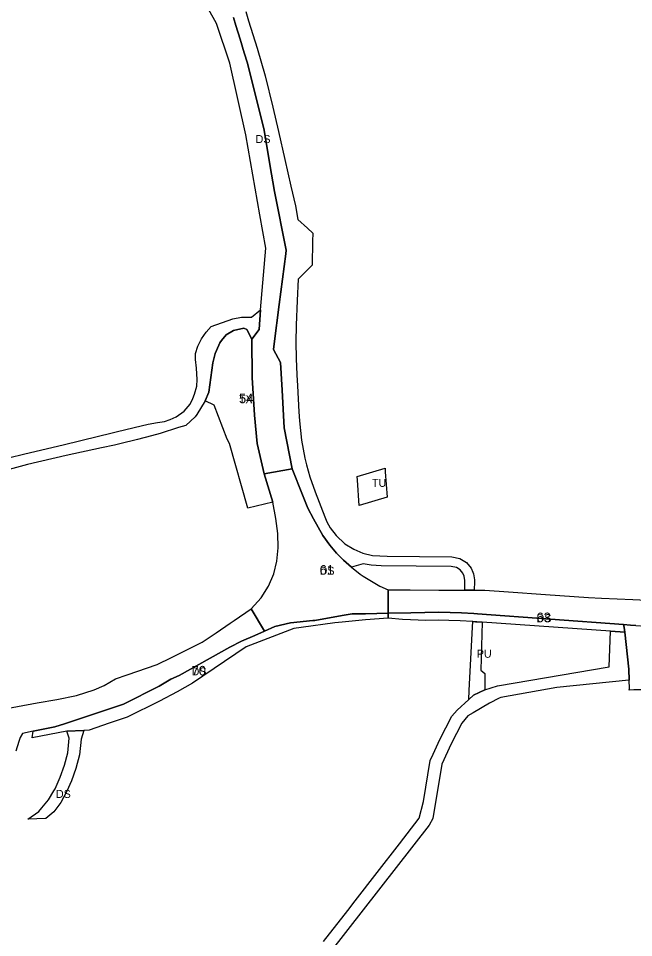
# Model space of a CAD drawing. Extents: x -535435 to -532834, y -1165802 to -1163866.
# Drawn here: x -534109 to -533724, y -1165015 to -1164441 of the extents above; entities that cross this region are included whole.
import ezdxf

# ---------------------------------------------------------------- set-up
doc = ezdxf.new("R2010")
doc.units = 0
for name, color, linetype in [('90320013', 7, 'Continuous'), ('90320023', 7, 'Continuous'), ('90380013', 7, 'Continuous'), ('90380023', 7, 'Continuous'), ('90440023', 7, 'Continuous'), ('90450013', 7, 'Continuous'), ('90450023', 7, 'Continuous'), ('ID_navrh', 7, 'Continuous')]:
    doc.layers.add(name, color=color, linetype=linetype)

msp = doc.modelspace()

# ---------------------------------------------------------------- linework, layer by layer
at = {"layer": '90320013'}
for points in [[(-533974.15, -1164440.11), (-533972.65, -1164445.05), (-533970.07, -1164453.5), (-533967.42, -1164462.17), (-533965.5, -1164468.47), (-533962.73, -1164479.54), (-533955.24, -1164509.41), (-533954.44, -1164514.16), (-533951.43, -1164531.95), (-533948.58, -1164548.78), (-533941.27, -1164585.42), (-533941.56, -1164587.64), (-533945.61, -1164619.41), (-533948.72, -1164643.84), (-533949.17, -1164647.34), (-533944.79, -1164655.52), (-533943.81, -1164672.76), (-533942.91, -1164688.74), (-533942.48, -1164696.43), (-533937.62, -1164722.08), (-533955.09, -1164725.13), (-533959.32, -1164706.09), (-533961.14, -1164688.48), (-533962.47, -1164664.91), (-533962.79, -1164640.92), (-533958.25, -1164634.91), (-533957.211, -1164622.742), (-533953.92, -1164584.19), (-533957.65, -1164563.22), (-533966.49, -1164513.4), (-533976.42, -1164468.54), (-533984.74, -1164443.86), (-533999.91, -1164416.7)], [(-533722.741, -1164819.796), (-533726.02, -1164819.56), (-533730.54, -1164819.23), (-533821.72, -1164812.62), (-533824.09, -1164812.44), (-533831.76, -1164811.89), (-533845.93, -1164811.47), (-533863.45, -1164811.86), (-533877.61, -1164812.17), (-533877.62, -1164797.66), (-533872.62, -1164797.667), (-533863.74, -1164797.68), (-533845.77, -1164797.71), (-533829.713, -1164797.731), (-533823.21, -1164797.74), (-533820.59, -1164797.75), (-533817.02, -1164797.76), (-533802.41, -1164798.81), (-533779.21, -1164800.48), (-533752.3, -1164802.43), (-533744.22, -1164802.78), (-533724.542, -1164803.644), (-533711.44, -1164804.22)]]:
    msp.add_lwpolyline(points, dxfattribs=at)
msp.add_lwpolyline([(-534067.68, -1164885.4), (-534069.42, -1164890.86), (-534070.43, -1164900.65), (-534072.79, -1164909.21), (-534075.53, -1164917.01), (-534078.29, -1164923.33), (-534082.19, -1164930.46), (-534086.44, -1164936.35), (-534091.39, -1164940.53), (-534102.62, -1164940.95), (-534095.94, -1164936.02), (-534093.96, -1164933.75), (-534089.86, -1164928.73), (-534086.47, -1164923.09), (-534085.73, -1164921.88), (-534082.42, -1164914.59), (-534079.81, -1164907.04), (-534077.66, -1164899.32), (-534076.97, -1164890.2), (-534078.33, -1164885.8)], close=True, dxfattribs=at)
at = {"layer": '90320023'}
for points in [[(-533966.526, -1164436.248), (-533964.719, -1164442.117), (-533962.096, -1164450.634), (-533959.457, -1164459.206), (-533954.432, -1164476.512), (-533949.559, -1164496.052), (-533946.1, -1164511.207), (-533942.1, -1164528.737), (-533938.311, -1164545.337), (-533935.477, -1164557.756), (-533933.924, -1164566.171), (-533928.047, -1164571.612), (-533924.633, -1164574.772), (-533924.728, -1164579.85), (-533925.006, -1164594.768), (-533928.175, -1164597.927), (-533933.845, -1164603.579), (-533934.374, -1164616.826), (-533935.021, -1164632.229), (-533935.27, -1164642.867), (-533935.108, -1164652.972), (-533934.702, -1164663.366), (-533934.278, -1164670.147), (-533933.268, -1164686.286), (-533932.906, -1164692.069), (-533931.627, -1164704.155), (-533929.632, -1164715.238), (-533928.481, -1164719.555), (-533926.509, -1164726.959), (-533923.227, -1164736.291), (-533917.13, -1164752.07), (-533915.848, -1164755.075), (-533913.837, -1164758.775), (-533910.072, -1164763.667), (-533904.657, -1164768.747), (-533899.011, -1164772.271), (-533893.292, -1164774.744), (-533887.252, -1164776.166), (-533878.083, -1164776.633), (-533837.659, -1164776.992), (-533832.654, -1164777.966), (-533828.577, -1164780.481), (-533825.628, -1164784), (-533824.518, -1164786.617), (-533824.147, -1164787.493), (-533823.649, -1164791.291), (-533823.66, -1164792.468), (-533823.713, -1164797.739), (-533829.713, -1164797.731), (-533829.653, -1164791.654), (-533829.99, -1164789.083), (-533830.802, -1164787.167), (-533832.553, -1164785.078), (-533834.874, -1164783.646), (-533838.263, -1164782.986), (-533881.993, -1164782.599), (-533888.18, -1164782.112), (-533893.097, -1164781.251), (-533900.403, -1164783.498), (-533905.409, -1164779.095), (-533909.763, -1164774.688), (-533913.989, -1164769.716), (-533918.274, -1164763.699), (-533924.264, -1164753.325), (-533927.756, -1164746.582), (-533931.134, -1164738.193), (-533937.62, -1164722.08), (-533942.48, -1164696.43), (-533942.91, -1164688.74), (-533943.81, -1164672.76), (-533944.79, -1164655.52), (-533949.17, -1164647.34), (-533948.72, -1164643.84), (-533945.61, -1164619.41), (-533941.56, -1164587.64), (-533941.27, -1164585.42), (-533948.58, -1164548.78), (-533951.43, -1164531.95), (-533954.44, -1164514.16), (-533955.24, -1164509.41), (-533962.73, -1164479.54), (-533965.5, -1164468.47), (-533967.42, -1164462.17), (-533970.07, -1164453.5), (-533972.65, -1164445.05), (-533974.15, -1164440.11)], [(-534114.899, -1164715.096), (-534104.663, -1164712.55), (-534080.73, -1164706.916), (-534058.603, -1164701.497), (-534050.857, -1164699.668), (-534047.573, -1164698.892), (-534036.347, -1164696.241), (-534027.567, -1164694.184), (-534021.634, -1164693.103), (-534017.22, -1164692.32), (-534013.67, -1164691.24), (-534010.017, -1164689.514), (-534004.94, -1164685.91), (-534001.2, -1164681.66), (-533999.598, -1164677.998), (-533998.47, -1164675.42), (-533997.1, -1164670.37), (-533996.9, -1164666.28), (-533997.34, -1164659.16), (-533997.92, -1164653.73), (-533997.86, -1164649.94), (-533996.38, -1164645.34), (-533994.23, -1164640.86), (-533991.34, -1164636.53), (-533988.116, -1164633.161), (-533974.64, -1164628.33), (-533969.29, -1164627.24), (-533963.011, -1164627.201), (-533957.211, -1164622.742), (-533958.25, -1164634.91), (-533962.79, -1164640.92), (-533965.769, -1164634.873), (-533967.69, -1164634.08), (-533974.09, -1164635.67), (-533978.83, -1164638.245), (-533981.729, -1164641.883), (-533982.7, -1164643.29), (-533984.794, -1164648.09), (-533985.58, -1164649.89), (-533987.09, -1164655.67), (-533989.59, -1164674.03), (-533991.85, -1164679.44), (-533997.187, -1164688.034), (-533998.16, -1164689.6), (-534004.077, -1164694.939), (-534008.472, -1164696.158), (-534019.931, -1164699.905), (-534025.36, -1164701.44), (-534034.205, -1164703.612), (-534045.29, -1164706.38), (-534048.46, -1164707.26), (-534056.646, -1164708.944), (-534078.701, -1164713.711), (-534102.862, -1164719.219), (-534114.467, -1164722.35)]]:
    msp.add_lwpolyline(points, dxfattribs=at)
for points in [[(-533954.918, -1164823.491), (-533963.1, -1164809.55), (-533956.938, -1164802.511), (-533952.293, -1164795.247), (-533949.047, -1164787.683), (-533947.08, -1164779.742), (-533946.273, -1164771.351), (-533946.509, -1164762.433), (-533947.667, -1164752.915), (-533949.63, -1164742.72), (-533955.09, -1164725.13), (-533937.62, -1164722.08), (-533931.134, -1164738.193), (-533927.756, -1164746.582), (-533924.264, -1164753.325), (-533918.274, -1164763.699), (-533913.989, -1164769.716), (-533909.763, -1164774.688), (-533905.409, -1164779.095), (-533900.403, -1164783.498), (-533894.971, -1164787.721), (-533893.072, -1164788.969), (-533882.672, -1164795.392), (-533877.62, -1164797.66), (-533877.61, -1164812.17), (-533891.74, -1164812.48), (-533900.11, -1164812.65), (-533906.24, -1164813.72), (-533923.29, -1164816.69), (-533924.69, -1164816.71), (-533938.49, -1164818.24), (-533948.29, -1164820.59)], [(-533877.61, -1164812.17), (-533877.617, -1164815.18), (-533891.706, -1164816.42), (-533906.182, -1164817.694), (-533910.91, -1164818.11), (-533931.848, -1164821.093), (-533936.53, -1164821.76), (-533960.78, -1164831.03), (-533966.36, -1164833.16), (-533999.79, -1164855.92), (-534009.46, -1164861.214), (-534020.45, -1164867.23), (-534040.68, -1164877.03), (-534051.898, -1164880.919), (-534064.45, -1164885.27), (-534067.68, -1164885.4), (-534078.33, -1164885.8), (-534099.92, -1164890.03), (-534099.32, -1164885.91), (-534085.85, -1164883.22), (-534079.77, -1164881.2), (-534064.74, -1164876.21), (-534042.95, -1164868.98), (-534020.66, -1164857.69), (-534013.44, -1164853.47), (-534008.11, -1164851.18), (-533976.56, -1164833.46), (-533969.12, -1164829.71), (-533960.9, -1164826.11), (-533954.918, -1164823.491), (-533948.29, -1164820.59), (-533938.49, -1164818.24), (-533924.69, -1164816.71), (-533923.29, -1164816.69), (-533906.24, -1164813.72), (-533900.11, -1164812.65), (-533891.74, -1164812.48)], [(-533877.61, -1164812.17), (-533863.45, -1164811.86), (-533845.93, -1164811.47), (-533831.76, -1164811.89), (-533824.09, -1164812.44), (-533821.72, -1164812.62), (-533730.54, -1164819.23), (-533730.04, -1164821.1), (-533729.7, -1164824.13), (-533738.69, -1164823.39), (-533818.847, -1164817.831), (-533822.155, -1164817.601), (-533822.99, -1164817.538), (-533824.567, -1164817.419), (-533824.726, -1164817.407), (-533824.861, -1164817.398), (-533832.622, -1164816.867), (-533839.714, -1164816.656), (-533846.109, -1164816.475), (-533854.091, -1164816.653), (-533863.514, -1164816.25), (-533868.666, -1164816.03), (-533877.617, -1164815.18)]]:
    msp.add_lwpolyline(points, close=True, dxfattribs=at)
at = {"layer": '90380013'}
msp.add_lwpolyline([(-533895.56, -1164744.9), (-533896.78, -1164729.16), (-533896.98, -1164726.69), (-533879.49, -1164721.65), (-533879.34, -1164723.78), (-533878.24, -1164739.68)], close=True, dxfattribs=at)
at = {"layer": '90380023'}
msp.add_lwpolyline([(-533917.983, -1165017.223), (-533902.835, -1164997.813), (-533898.225, -1164991.906), (-533884.317, -1164974.086), (-533870.466, -1164956.339), (-533858.16, -1164940.26), (-533855.511, -1164929.84), (-533851.211, -1164904.246), (-533849.336, -1164900.158), (-533846.247, -1164893.426), (-533845.178, -1164891.097), (-533837.807, -1164876.568), (-533834.51, -1164872.77), (-533827.206, -1164866.027), (-533824.163, -1164863.424), (-533817.166, -1164859.962), (-533809.264, -1164857.538), (-533739.473, -1164845.641), (-533738.69, -1164823.39), (-533729.7, -1164824.13), (-533727.12, -1164847.21), (-533726.9, -1164854), (-533727.16, -1164854.1), (-533772.11, -1164858.69), (-533807.19, -1164864.79), (-533808.265, -1164865.356), (-533814.12, -1164868.44), (-533824.38, -1164874.44), (-533827.73, -1164876.4), (-533831.54, -1164880.79), (-533838.18, -1164893.83), (-533843.98, -1164906.47), (-533849.69, -1164940.46), (-533851.83, -1164944.65), (-533913.79, -1165024.04)], dxfattribs=at)
at = {"layer": '90440023'}
msp.add_lwpolyline([(-533965.282, -1164746.513), (-533976.638, -1164706.229), (-533978.18, -1164703.55), (-533986.32, -1164682.27), (-533991.85, -1164679.44), (-533989.59, -1164674.03), (-533987.09, -1164655.67), (-533985.58, -1164649.89), (-533984.794, -1164648.09), (-533982.7, -1164643.29), (-533981.729, -1164641.883), (-533978.83, -1164638.245), (-533974.09, -1164635.67), (-533967.69, -1164634.08), (-533965.769, -1164634.873), (-533962.79, -1164640.92), (-533962.47, -1164664.91), (-533961.14, -1164688.48), (-533959.32, -1164706.09), (-533955.09, -1164725.13), (-533949.63, -1164742.72), (-533954.82, -1164744.13)], close=True, dxfattribs=at)
at = {"layer": '90450013'}
msp.add_lwpolyline([(-534121.57, -1164872.72), (-534096.94, -1164868.25), (-534084.65, -1164866.02), (-534072.3, -1164863.66), (-534061.28, -1164860.07), (-534055.1, -1164857.37), (-534047.9, -1164853.22), (-534040.68, -1164850.74), (-534021.84, -1164844.27), (-534012.98, -1164839.86), (-533996.77, -1164831.8), (-533993.8, -1164830.33), (-533985, -1164824.37), (-533976.3, -1164818.48), (-533973.78, -1164816.77), (-533963.1, -1164809.55), (-533954.918, -1164823.491), (-533960.9, -1164826.11), (-533969.12, -1164829.71), (-533976.56, -1164833.46), (-534008.11, -1164851.18), (-534013.44, -1164853.47), (-534020.66, -1164857.69), (-534042.95, -1164868.98), (-534064.74, -1164876.21), (-534079.77, -1164881.2), (-534085.85, -1164883.22), (-534099.32, -1164885.91), (-534106.11, -1164887.27), (-534107.59, -1164889.81), (-534108.18, -1164891.67), (-534108.42, -1164892.42), (-534110.31, -1164898.33)], dxfattribs=at)
msp.add_lwpolyline([(-533819.587, -1164847.865), (-533817.069, -1164849.817), (-533817.166, -1164859.962), (-533824.163, -1164863.424), (-533827.206, -1164866.027), (-533826.93, -1164860.55), (-533824.9, -1164820.82), (-533824.567, -1164817.419), (-533822.99, -1164817.538), (-533822.155, -1164817.601), (-533818.847, -1164817.831)], close=True, dxfattribs=at)
at = {"layer": '90450023'}
msp.add_lwpolyline([(-533730.54, -1164819.23), (-533726.02, -1164819.56), (-533722.741, -1164819.796), (-533716.647, -1164820.234), (-533716.135, -1164825.246), (-533716.102, -1164825.575), (-533715.547, -1164831.013), (-533713.818, -1164847.949), (-533712.834, -1164857.586), (-533717.48, -1164860.13), (-533724, -1164860.16), (-533726.94, -1164860.18), (-533726.73, -1164859.25), (-533726.9, -1164854), (-533727.12, -1164847.21), (-533729.7, -1164824.13), (-533730.04, -1164821.1)], close=True, dxfattribs=at)

# ---------------------------------------------------------------- texts
at = {"layer": '90320013'}
for rotation, p in [(360, (-533960.365, -1164518.4453)), (0, (-534085.15, -1164927.5824))]:
    msp.add_text('DS', height=5, rotation=rotation, dxfattribs=at).set_placement(p)
at = {"layer": '90320023'}
msp.add_text('DS', height=5, dxfattribs=at).set_placement((-533920.355, -1164788.1368))
for rotation, p in [(360, (-533784.7793, -1164817.8)), (359.9999999, (-534000.339, -1164851.1))]:
    msp.add_text('DS', height=5, rotation=rotation, dxfattribs=at).set_placement(p)
at = {"layer": '90380013'}
msp.add_text('TU', height=5, rotation=0, dxfattribs=at).set_placement((-533887.61, -1164733.2469))
at = {"layer": '90440023'}
msp.add_text('TX', height=5, rotation=0, dxfattribs=at).set_placement((-533970.74, -1164680.9946))
at = {"layer": '90450013'}
msp.add_text('PU', height=5, rotation=359.9999999, dxfattribs=at).set_placement((-533822.1375, -1164840.012))
at = {"layer": 'ID_navrh'}
for s, p in [('54', (-533970.74, -1164680.9946)), ('61', (-533920.355, -1164788.1368)), ('63', (-533784.7793, -1164817.8)), ('70', (-534000.339, -1164851.1))]:
    msp.add_text(s, height=6, rotation=360, dxfattribs=at).set_placement(p)

doc.saveas('drawing.dxf')
